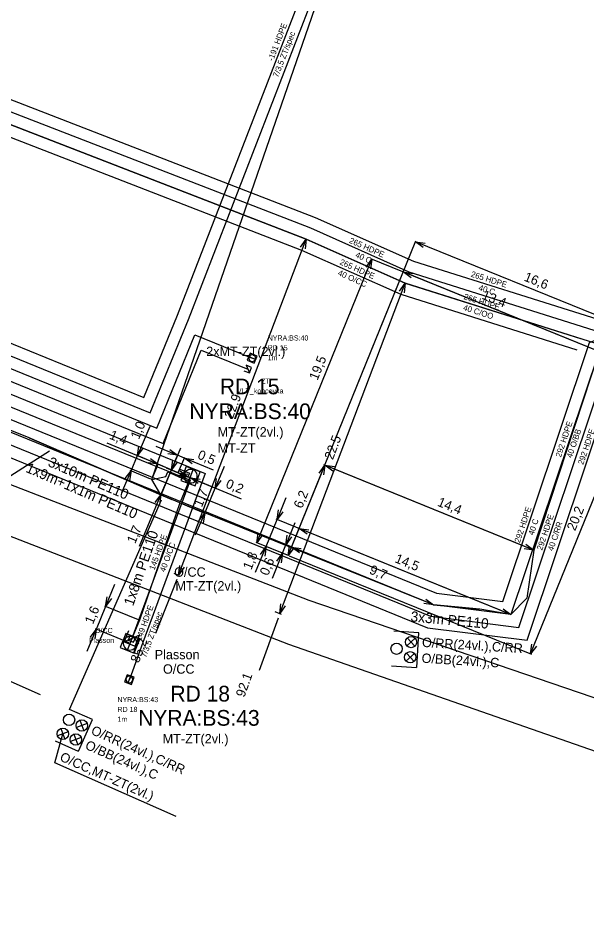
# Model space of a CAD drawing. Extents: x -836739 to -834468, y -1071001 to -1070126.
# Drawn here: x -836298 to -836261.8, y -1070459.3 to -1070401.3 of the extents above; entities that cross this region are included whole.
import ezdxf

# ---------------------------------------------------------------- set-up
doc = ezdxf.new("R2010")
doc.units = 0
for name, color, linetype in [('f001_pol_linie', 7, 'Continuous'), ('f002_inz_linie_mimo_CETIN', 7, 'Continuous'), ('f003_opt_sit_texty', 7, 'Continuous'), ('f003_opt_sit_znacky', 7, 'Continuous'), ('f006_osa_trasy', 7, 'Continuous'), ('f006_stp_koty', 7, 'Continuous'), ('f006_stp_linie', 7, 'Continuous'), ('f006_stp_texty', 7, 'Continuous'), ('f007_rezkynet_linie', 7, 'Continuous'), ('f007_rezkynet_texty', 7, 'Continuous'), ('f007_rezkynet_znacky', 7, 'Continuous'), ('f309_rozvadec_opt', 7, 'Continuous'), ('f309_rozvadec_opt_ann', 7, 'Continuous'), ('f309_trub_konc_zar', 7, 'Continuous'), ('f309_trub_konc_zar_ann', 7, 'Continuous'), ('f309_trubicka', 7, 'Continuous'), ('f309_trubicka_ann', 7, 'Continuous'), ('f309_trubka', 7, 'Continuous'), ('f309_trubka_ann', 7, 'Continuous')]:
    doc.layers.add(name, color=color, linetype=linetype)

msp = doc.modelspace()

# ---------------------------------------------------------------- linework, layer by layer
at = {"layer": 'f001_pol_linie'}
for points in [[(-836015.21, -1070459.49), (-836021.84, -1070470.53), (-836029.29, -1070480.55), (-836039.31, -1070497.89), (-836043.1, -1070509.87), (-836044.22, -1070522.08), (-836111.13, -1070487.77), (-836123.74, -1070483.53), (-836128.61, -1070481.99), (-836211.76, -1070460.38), (-836245.95, -1070449.75), (-836279.43, -1070438.33), (-836363.94, -1070405.58)], [(-836046.6, -1070544.35), (-836045.64, -1070538.23), (-836044.38, -1070528.39), (-836045.14, -1070525.37), (-836047.92, -1070523.71), (-836112.97, -1070490.6), (-836124.66, -1070486.54), (-836132.47, -1070484.33), (-836212.77, -1070463.28), (-836247.95, -1070452.55), (-836280.73, -1070441.12), (-836361.89, -1070409.63)]]:
    msp.add_lwpolyline(points, dxfattribs=at)
at = {"layer": 'f002_inz_linie_mimo_CETIN'}
for points in [[(-836287.77, -1070430.19), (-836287.67, -1070429.96), (-836287.05, -1070430.22), (-836287.15, -1070430.45)], [(-836287.77, -1070430.19), (-836287.67, -1070429.96), (-836287.05, -1070430.22), (-836287.15, -1070430.45)], [(-836287.77, -1070430.19), (-836287.15, -1070430.45)], [(-836287.77, -1070430.19), (-836287.15, -1070430.45)]]:
    msp.add_lwpolyline(points, dxfattribs=at)
at = {"layer": 'f003_opt_sit_znacky'}
for p, q in [((-836286.84, -1070430.005), (-836287.14, -1070430.815)), ((-836286.84, -1070430.006), (-836286.84, -1070430.005)), ((-836290.233, -1070440.531), (-836291.207, -1070440.949)), ((-836290.68, -1070440.639), (-836291, -1070441.441)), ((-836290.68, -1070440.64), (-836290.68, -1070440.639))]:
    msp.add_line(p, q, dxfattribs=at)
for points in [[(-836287.604, -1070430.694), (-836286.704, -1070431.028), (-836286.371, -1070430.127), (-836287.271, -1070429.794)], [(-836291.462, -1070441.308), (-836290.57, -1070441.665), (-836290.214, -1070440.774), (-836291.105, -1070440.417)]]:
    msp.add_lwpolyline(points, close=True, dxfattribs=at)
msp.add_lwpolyline([(-836290.929, -1070440.253), (-836291.207, -1070440.949), (-836290.511, -1070441.227), (-836290.233, -1070440.531)], dxfattribs=at)
for centre, start, end in [((-836286.987, -1070430.411), 70.04066, 249.31307), ((-836286.987, -1070430.411), 249.27232, 70.08055), ((-836290.837, -1070441.041), 68.56239, 247.83479), ((-836290.837, -1070441.042), 247.79404, 68.60228)]:
    msp.add_arc(centre, 0.432, start, end, dxfattribs=at)
at = {"layer": 'f006_osa_trasy'}
for points in [[(-836259.51, -1070422.49), (-836273.33, -1070418.13), (-836279.63, -1070415.33), (-836305.65, -1070405.26), (-836332.15, -1070395.46), (-836355.51, -1070386.15), (-836363.32, -1070381.37), (-836370.68, -1070374.62), (-836386.63, -1070361.4), (-836412.6, -1070344.19), (-836444.52, -1070318.16), (-836450.35, -1070293.64), (-836451.12, -1070284.95), (-836453.47, -1070277.02), (-836456.68, -1070270.62)], [(-836289.45, -1070430.62), (-836275.81, -1070391.2), (-836278.03, -1070390.26), (-836275.63, -1070384.47)], [(-836288.87, -1070431.6), (-836297.25, -1070427.97), (-836320.19, -1070418.75)], [(-836259.51, -1070422.49), (-836260.99, -1070422.47), (-836265.14, -1070435.11), (-836265.59, -1070438.17), (-836266.6, -1070439.21), (-836268.57, -1070438.87), (-836271.52, -1070438.59), (-836287.66, -1070432.1)], [(-836289.45, -1070430.62), (-836288.57, -1070430.43), (-836288.43, -1070430.13), (-836287.11, -1070430.72), (-836286.99, -1070430.41)], [(-836288.87, -1070431.6), (-836289.45, -1070430.62)], [(-836287.66, -1070432.1), (-836288.18, -1070431.9), (-836288.87, -1070431.6)], [(-836287.66, -1070432.1), (-836290.24, -1070439.58), (-836290.72, -1070440.74)], [(-836290.72, -1070440.74), (-836290.84, -1070441.04)]]:
    msp.add_lwpolyline(points, dxfattribs=at)
at = {"layer": 'f006_stp_koty'}
for p, q in [((-836280.747, -1070435.404), (-836272.651, -1070415.438)), ((-836257.247, -1070421.749), (-836272.673, -1070415.494)), ((-836282.764, -1070434.651), (-836275.447, -1070416.607)), ((-836261.046, -1070422.447), (-836275.503, -1070416.585)), ((-836280.747, -1070435.404), (-836273.43, -1070417.361)), ((-836260.99, -1070422.47), (-836273.453, -1070417.416)), ((-836265.343, -1070441.716), (-836257.77, -1070423.04)), ((-836289.584, -1070427.238), (-836290.366, -1070429.101)), ((-836292.317, -1070428.283), (-836289.045, -1070429.655)), ((-836289.196, -1070428.499), (-836287.813, -1070429.079)), ((-836287.623, -1070428.625), (-836288.203, -1070430.009)), ((-836290.771, -1070430.066), (-836290.366, -1070429.101)), ((-836287.825, -1070430.167), (-836290.421, -1070429.078)), ((-836288.847, -1070431.545), (-836287.79, -1070429.024)), ((-836287.38, -1070429.26), (-836287.813, -1070429.079)), ((-836287.747, -1070430.135), (-836287.357, -1070429.205)), ((-836285.527, -1070430.037), (-836287.38, -1070429.26)), ((-836291.351, -1070431.449), (-836290.771, -1070430.066)), ((-836289.505, -1070430.597), (-836290.826, -1070430.043)), ((-836289.427, -1070430.565), (-836289.022, -1070429.6)), ((-836287.77, -1070430.19), (-836289.045, -1070429.655)), ((-836288.87, -1070431.6), (-836288.203, -1070430.009)), ((-836288.533, -1070429.87), (-836287.15, -1070430.45)), ((-836287.825, -1070430.167), (-836288.258, -1070429.985)), ((-836284.843, -1070429.791), (-836285.423, -1070431.174)), ((-836280.77, -1070435.46), (-836278.441, -1070429.716)), ((-836280.747, -1070435.404), (-836278.418, -1070429.661)), ((-836265.196, -1070435.087), (-836278.496, -1070429.694)), ((-836265.14, -1070435.11), (-836278.441, -1070429.716)), ((-836286.387, -1070430.77), (-836287.77, -1070430.19)), ((-836287.637, -1070432.045), (-836286.972, -1070430.46)), ((-836287.15, -1070430.45), (-836286.995, -1070430.515)), ((-836287.095, -1070430.473), (-836285.367, -1070431.198)), ((-836283.738, -1070431.881), (-836286.995, -1070430.515)), ((-836286.088, -1070432.759), (-836285.423, -1070431.174)), ((-836290.237, -1070434.86), (-836288.87, -1070431.6)), ((-836280.922, -1070431.784), (-836281.485, -1070433.174)), ((-836287.605, -1070432.123), (-836286.032, -1070432.783)), ((-836286.668, -1070434.143), (-836286.088, -1070432.759)), ((-836282.181, -1070434.888), (-836281.485, -1070433.174)), ((-836266.656, -1070439.187), (-836281.541, -1070433.151)), ((-836280.355, -1070433.389), (-836280.919, -1070434.779)), ((-836280.747, -1070435.404), (-836280.052, -1070433.69)), ((-836266.6, -1070439.21), (-836280.075, -1070433.746)), ((-836280.826, -1070435.437), (-836282.82, -1070434.629)), ((-836281.135, -1070435.312), (-836280.919, -1070434.779)), ((-836271.576, -1070438.567), (-836280.974, -1070434.756)), ((-836282.846, -1070436.528), (-836282.181, -1070434.888)), ((-836280.826, -1070435.437), (-836282.236, -1070434.865)), ((-836281.777, -1070436.895), (-836281.135, -1070435.312)), ((-836280.826, -1070435.437), (-836281.191, -1070435.289)), ((-836280.747, -1070435.404), (-836280.531, -1070434.871)), ((-836271.52, -1070438.59), (-836280.554, -1070434.927)), ((-836280.714, -1070435.483), (-836265.288, -1070441.738)), ((-836291.821, -1070437.309), (-836292.391, -1070438.696)), ((-836292.391, -1070438.696), (-836292.991, -1070440.156)), ((-836290.295, -1070439.557), (-836292.447, -1070438.673)), ((-836293.561, -1070441.543), (-836292.991, -1070440.156)), ((-836290.895, -1070441.017), (-836293.047, -1070440.133))]:
    msp.add_line(p, q, dxfattribs=at)
for points in [[(-836287.75, -1070436.714), (-836279.63, -1070415.329)], [(-836279.983, -1070415.836), (-836279.63, -1070415.329), (-836279.702, -1070415.943)], [(-836272.174, -1070415.858), (-836272.673, -1070415.494), (-836272.061, -1070415.58)], [(-836275.812, -1070417.107), (-836275.447, -1070416.607), (-836275.534, -1070417.22)], [(-836272.953, -1070417.781), (-836273.453, -1070417.416), (-836272.841, -1070417.503)], [(-836281.315, -1070439.158), (-836273.329, -1070418.13)], [(-836273.682, -1070418.637), (-836273.329, -1070418.13), (-836273.401, -1070418.744)], [(-836289.996, -1070428.606), (-836290.366, -1070429.101), (-836290.272, -1070428.49)], [(-836288.308, -1070428.708), (-836287.813, -1070429.079), (-836288.424, -1070428.985)], [(-836289.541, -1070429.285), (-836289.045, -1070429.655), (-836289.657, -1070429.561)], [(-836287.832, -1070429.513), (-836288.203, -1070430.009), (-836288.109, -1070429.397)], [(-836286.885, -1070429.631), (-836287.38, -1070429.26), (-836286.769, -1070429.354)], [(-836291.141, -1070430.561), (-836290.771, -1070430.066), (-836290.864, -1070430.678)], [(-836287.645, -1070430.08), (-836287.15, -1070430.45), (-836287.761, -1070430.356)], [(-836278.805, -1070430.216), (-836278.441, -1070429.716), (-836278.527, -1070430.329)], [(-836277.941, -1070430.081), (-836278.441, -1070429.716), (-836277.828, -1070429.803)], [(-836287.275, -1070430.56), (-836287.77, -1070430.19), (-836287.159, -1070430.284)], [(-836286.5, -1070430.885), (-836286.995, -1070430.515), (-836286.384, -1070430.609)], [(-836285.052, -1070430.679), (-836285.423, -1070431.174), (-836285.329, -1070430.563)], [(-836289.24, -1070432.095), (-836288.87, -1070431.6), (-836288.964, -1070432.211)], [(-836286.458, -1070433.255), (-836286.088, -1070432.759), (-836286.181, -1070433.371)], [(-836281.121, -1070432.674), (-836281.485, -1070433.174), (-836281.399, -1070432.561)], [(-836282.4, -1070434.152), (-836282.764, -1070434.651), (-836282.678, -1070434.039)], [(-836280.554, -1070434.279), (-836280.919, -1070434.779), (-836280.832, -1070434.166)], [(-836279.575, -1070434.11), (-836280.075, -1070433.746), (-836279.462, -1070433.832)], [(-836265.64, -1070434.746), (-836265.14, -1070435.11), (-836265.752, -1070435.024)], [(-836282.545, -1070435.388), (-836282.181, -1070434.888), (-836282.267, -1070435.5)], [(-836281.5, -1070435.812), (-836281.135, -1070435.312), (-836281.222, -1070435.924)], [(-836280.406, -1070434.96), (-836280.77, -1070435.46), (-836280.684, -1070434.848)], [(-836280.054, -1070435.291), (-836280.554, -1070434.927), (-836279.941, -1070435.013)], [(-836287.396, -1070436.206), (-836287.75, -1070436.714), (-836287.677, -1070436.099)], [(-836287.861, -1070436.993), (-836289.213, -1070440.431)], [(-836287.787, -1070436.7), (-836288.031, -1070436.607)], [(-836292.024, -1070438.198), (-836292.391, -1070438.696), (-836292.302, -1070438.084)], [(-836272.02, -1070438.226), (-836271.52, -1070438.59), (-836272.132, -1070438.504)], [(-836280.961, -1070438.65), (-836281.315, -1070439.158), (-836281.242, -1070438.543)], [(-836267.1, -1070438.846), (-836266.6, -1070439.21), (-836267.212, -1070439.124)], [(-836281.193, -1070439.205), (-836281.596, -1070439.052)], [(-836281.418, -1070439.441), (-836282.619, -1070442.776)], [(-836293.358, -1070440.654), (-836292.991, -1070440.156), (-836293.081, -1070440.768)], [(-836264.979, -1070441.216), (-836265.343, -1070441.716), (-836265.257, -1070441.103)]]:
    msp.add_lwpolyline(points, dxfattribs=at)
at = {"layer": 'f006_stp_linie'}
for points in [[(-836297.25, -1070427.97), (-836288.87, -1070431.6)], [(-836288.87, -1070431.6), (-836288.18, -1070431.9)], [(-836287.66, -1070432.1), (-836290.24, -1070439.58)], [(-836271.52, -1070438.59), (-836268.57, -1070438.87)]]:
    msp.add_lwpolyline(points, dxfattribs=at)
at = {"layer": 'f007_rezkynet_linie'}
for points in [[(-836307.058, -1070435.86), (-836295.973, -1070428.796)], [(-836294.699, -1070445.249), (-836288.84, -1070431.91)], [(-836296.531, -1070444.332), (-836307.992, -1070439.257), (-836307.472, -1070437.416)], [(-836287.9, -1070452.07), (-836295.633, -1070448.646), (-836295.113, -1070446.805)]]:
    msp.add_lwpolyline(points, dxfattribs=at)
at = {"layer": 'f007_rezkynet_znacky'}
for p, q in [((-836272.456, -1070440.375), (-836274.053, -1070440.275)), ((-836272.594, -1070442.577), (-836272.456, -1070440.375)), ((-836272.682, -1070440.724), (-836273.226, -1070441.205)), ((-836273.194, -1070440.693), (-836272.713, -1070441.236)), ((-836272.732, -1070441.693), (-836273.276, -1070442.174)), ((-836273.244, -1070441.662), (-836272.763, -1070442.205)), ((-836274.207, -1070442.477), (-836272.61, -1070442.576)), ((-836293.236, -1070445.897), (-836294.699, -1070445.249)), ((-836293.568, -1070446.147), (-836294.246, -1070446.408)), ((-836294.129, -1070447.915), (-836293.236, -1070445.897)), ((-836294.038, -1070445.939), (-836293.776, -1070446.616)), ((-836294.774, -1070446.674), (-836295.452, -1070446.935)), ((-836295.244, -1070446.466), (-836294.982, -1070447.143)), ((-836294.422, -1070446.83), (-836294.159, -1070447.507)), ((-836295.607, -1070447.261), (-836294.144, -1070447.908)), ((-836293.952, -1070447.038), (-836294.629, -1070447.299))]:
    msp.add_line(p, q, dxfattribs=at)
for centre in [(-836273.872, -1070441.389), (-836272.954, -1070440.965), (-836273.004, -1070441.933), (-836294.721, -1070445.917), (-836293.907, -1070446.278), (-836295.113, -1070446.805), (-836294.291, -1070447.169)]:
    msp.add_circle(centre, 0.363, dxfattribs=at)
at = {"layer": 'f309_rozvadec_opt'}
for p, q in [((-836282.861, -1070422.981), (-836283.261, -1070422.818)), ((-836282.862, -1070422.981), (-836282.861, -1070422.981)), ((-836290.954, -1070443.552), (-836290.805, -1070443.147)), ((-836290.954, -1070443.552), (-836290.954, -1070443.552))]:
    msp.add_line(p, q, dxfattribs=at)
for points in [[(-836283.193, -1070422.588), (-836283.375, -1070423.032), (-836282.93, -1070423.214), (-836282.749, -1070422.769)], [(-836290.573, -1070443.207), (-836291.023, -1070443.041), (-836291.189, -1070443.491), (-836290.738, -1070443.657)]]:
    msp.add_lwpolyline(points, close=True, dxfattribs=at)
for centre, start, end in [((-836283.062, -1070422.901), 157.39472, 338.20296), ((-836283.062, -1070422.901), 338.16306, 157.43547), ((-836290.881, -1070443.349), 69.38754, 250.19578), ((-836290.881, -1070443.349), 250.15589, 69.42829)]:
    msp.add_arc(centre, 0.216, start, end, dxfattribs=at)
at = {"layer": 'f309_trub_konc_zar'}
for p, q in [((-836283.448, -1070423.351), (-836283.242, -1070423.839)), ((-836290.479, -1070440.629), (-836290.961, -1070440.851))]:
    msp.add_line(p, q, dxfattribs=at)
for points in [[(-836283.589, -1070423.698), (-836283.242, -1070423.839), (-836283.101, -1070423.492), (-836283.448, -1070423.351)], [(-836290.831, -1070440.499), (-836290.961, -1070440.851), (-836290.609, -1070440.981), (-836290.479, -1070440.629)]]:
    msp.add_lwpolyline(points, dxfattribs=at)
at = {"layer": 'f309_trubicka'}
for points in [[(-836400.273, -1070369.489), (-836399.069, -1070370.656), (-836400.13, -1070374.016), (-836402.617, -1070381.89), (-836396.907, -1070384.038), (-836379.536, -1070393.352), (-836349.287, -1070404.44), (-836286.052, -1070430.233), (-836290.016, -1070440.999), (-836290.881, -1070443.349)], [(-836400.273, -1070369.489), (-836396.208, -1070371.559), (-836397.27, -1070374.92), (-836399.339, -1070381.472), (-836399.355, -1070381.515), (-836396.285, -1070382.67), (-836378.92, -1070391.98), (-836348.745, -1070403.04), (-836289.137, -1070427.354), (-836286.713, -1070421.411), (-836283.062, -1070422.901)], [(-836400.273, -1070369.489), (-836394.777, -1070372.011), (-836395.84, -1070375.372), (-836397.495, -1070380.612), (-836395.663, -1070381.302), (-836378.304, -1070390.608), (-836348.203, -1070401.64), (-836289.959, -1070425.398), (-836287.821, -1070420.156), (-836276.772, -1070391.607), (-836279.008, -1070390.66), (-836276.322, -1070384.183), (-836278.31, -1070383.359), (-836277.858, -1070382.269)], [(-836400.273, -1070369.489), (-836395.493, -1070371.785), (-836396.555, -1070375.146), (-836398.424, -1070381.064), (-836395.974, -1070381.986), (-836378.612, -1070391.294), (-836348.474, -1070402.34), (-836289.548, -1070426.376), (-836287.124, -1070420.433), (-836275.81, -1070391.2), (-836278.03, -1070390.26), (-836275.63, -1070384.47), (-836273.812, -1070385.224), (-836273.367, -1070384.131)], [(-836397.141, -1070372.024), (-836397.985, -1070374.694), (-836400.049, -1070381.229), (-836400.305, -1070381.924), (-836400.312, -1070381.956), (-836396.596, -1070383.354), (-836379.228, -1070392.666), (-836349.016, -1070403.74), (-836288.726, -1070428.332), (-836286.302, -1070422.389), (-836283.345, -1070423.595)]]:
    msp.add_lwpolyline(points, dxfattribs=at)
at = {"layer": 'f309_trubka'}
for points in [[(-836261.299, -1070421.137), (-836273.064, -1070417.427), (-836279.342, -1070414.637), (-836305.385, -1070404.559), (-836331.881, -1070394.76), (-836354.106, -1070385.902), (-836354.759, -1070385.663), (-836362.708, -1070381.226), (-836386.046, -1070360.976), (-836412.515, -1070343.515), (-836444.58, -1070317.908), (-836450.178, -1070294.362), (-836450.35, -1070293.64), (-836451.12, -1070284.95), (-836453.47, -1070277.02), (-836455.659, -1070272.655)], [(-836454.989, -1070272.319), (-836452.77, -1070276.743), (-836450.38, -1070284.809), (-836449.608, -1070293.52), (-836449.436, -1070294.242), (-836443.91, -1070317.483), (-836412.074, -1070342.908), (-836385.592, -1070360.377), (-836362.275, -1070380.609), (-836354.445, -1070384.979), (-836353.838, -1070385.201), (-836331.612, -1070394.06), (-836305.12, -1070403.858), (-836279.054, -1070413.944), (-836272.798, -1070416.724), (-836261.073, -1070420.421)], [(-836457, -1070273.327), (-836454.87, -1070277.574), (-836452.6, -1070285.232), (-836451.834, -1070293.88), (-836451.663, -1070294.602), (-836445.92, -1070318.758), (-836413.397, -1070344.729), (-836386.954, -1070362.174), (-836363.574, -1070382.46), (-836355.387, -1070387.031), (-836354.642, -1070387.304), (-836332.419, -1070396.16), (-836305.915, -1070405.961), (-836279.918, -1070416.023), (-836273.596, -1070418.833), (-836262.401, -1070422.363)], [(-836456.329, -1070272.991), (-836454.17, -1070277.297), (-836451.86, -1070285.091), (-836451.092, -1070293.76), (-836445.25, -1070318.333), (-836412.956, -1070344.122), (-836386.5, -1070361.575), (-836363.141, -1070381.843), (-836355.073, -1070386.347), (-836354.374, -1070386.603), (-836332.15, -1070395.46), (-836305.65, -1070405.26), (-836279.63, -1070415.33), (-836273.33, -1070418.13), (-836262.175, -1070421.648)], [(-836257.543, -1070422.322), (-836258.258, -1070422.096), (-836259.283, -1070421.772), (-836260.99, -1070422.47), (-836266.6, -1070439.21), (-836271.52, -1070438.59), (-836350.1, -1070406.54), (-836380.46, -1070395.41), (-836397.84, -1070386.09), (-836408, -1070382.27), (-836428.93, -1070370.15), (-836446.35, -1070358.45), (-836497.8, -1070313.84), (-836500.259, -1070310.812)], [(-836499.139, -1070311.001), (-836497.259, -1070313.316), (-836445.894, -1070357.853), (-836428.533, -1070369.513), (-836407.678, -1070381.59), (-836397.529, -1070385.406), (-836380.152, -1070394.724), (-836349.829, -1070405.84), (-836271.328, -1070437.858), (-836267.116, -1070438.389), (-836261.592, -1070421.906), (-836259.316, -1070420.975), (-836258.032, -1070421.38), (-836257.317, -1070421.606)], [(-836501.069, -1070312.194), (-836498.882, -1070314.888), (-836447.262, -1070359.644), (-836429.724, -1070371.424), (-836408.644, -1070383.63), (-836398.462, -1070387.458), (-836381.076, -1070396.782), (-836350.642, -1070407.94), (-836271.904, -1070440.054), (-836265.568, -1070440.852), (-836259.786, -1070423.598), (-836259.218, -1070423.366), (-836257.995, -1070423.753)], [(-836499.902, -1070312.441), (-836498.341, -1070314.364), (-836446.806, -1070359.047), (-836429.327, -1070370.787), (-836408.322, -1070382.95), (-836398.151, -1070386.774), (-836380.768, -1070396.096), (-836350.371, -1070407.24), (-836271.712, -1070439.322), (-836266.084, -1070440.031), (-836260.388, -1070423.034), (-836259.25, -1070422.569), (-836257.769, -1070423.038)], [(-836400.845, -1070373.79), (-836403.452, -1070382.042), (-836403.525, -1070382.35), (-836397.218, -1070384.722), (-836379.844, -1070394.038), (-836349.558, -1070405.14), (-836287.006, -1070430.654), (-836290.72, -1070440.74)]]:
    msp.add_lwpolyline(points, dxfattribs=at)

# ---------------------------------------------------------------- texts
at = {"layer": 'f003_opt_sit_texty'}
for s, height, p in [('2xMT-ZT(2vl.)', 0.6, (-836285.99, -1070422.77)), ('RD 15', 1, (-836285.12, -1070425.2)), ('NYRA:BS:40', 1, (-836287.06, -1070426.78)), ('MT-ZT(2vl.)', 0.6, (-836285.26, -1070427.89)), ('MT-ZT', 0.6, (-836285.26, -1070428.92)), ('O/CC', 0.6, (-836288.03, -1070436.81)), ('MT-ZT(2vl.)', 0.6, (-836287.95, -1070437.69)), ('Plasson', 0.6, (-836289.27, -1070442.06)), ('O/CC', 0.6, (-836288.74, -1070442.98)), ('RD 18', 1, (-836288.27, -1070444.75)), ('NYRA:BS:43', 1, (-836290.32, -1070446.29)), ('MT-ZT(2vl.)', 0.6, (-836288.76, -1070447.42))]:
    msp.add_text(s, height=height, dxfattribs=at).set_placement(p)
at = {"layer": 'f006_stp_koty'}
for s, rotation, p in [('16,6', 337.92686, (-836265.812, -1070417.952)), ('13,4', 337.92686, (-836268.488, -1070419.106)), ('19,5', 67.92686, (-836278.911, -1070424.351)), ('22.9', 69.21, (-836284.302, -1070426.786)), ('1,0', 67.24902, (-836290.276, -1070428.11)), ('1,4', 337.24902, (-836292.201, -1070428.006)), ('22.5', 69.2, (-836277.934, -1070429.409)), ('0,5', 337.24902, (-836286.587, -1070429.267)), ('0,2', 337.24902, (-836284.798, -1070431.111)), ('1,7', 67.24902, (-836286.271, -1070432.422)), ('6,2', 67.92686, (-836279.897, -1070432.509)), ('14,4', 337.92686, (-836271.321, -1070432.28)), ('20,2', 67.92686, (-836262.51, -1070433.93)), ('1,7', 67.24902, (-836290.514, -1070434.744)), ('1,8', 67.92686, (-836283.124, -1070436.415)), ('0,6', 67.92686, (-836282.055, -1070436.783)), ('14,5', 337.92686, (-836274.03, -1070435.873)), ('9,7', 337.92686, (-836275.654, -1070436.59)), ('1,6', 67.65935, (-836293.197, -1070439.868)), ('85.2', 68.53, (-836290.285, -1070442.336)), ('92.1', 70.19, (-836283.566, -1070444.521))]:
    msp.add_text(s, height=0.6, rotation=rotation, dxfattribs=at).set_placement(p)
at = {"layer": 'f006_stp_texty'}
for s, rotation, p in [('3x10m PE110', 336.57898, (-836296.115, -1070429.748)), ('1x9m+1x1m PE110', 336.57898, (-836297.523, -1070430.123)), ('1x8m PE110', 70.96967, (-836290.645, -1070438.712)), ('3x3m PE110', 354.578, (-836273.003, -1070439.648))]:
    msp.add_text(s, height=0.65, rotation=rotation, dxfattribs=at).set_placement(p)
at = {"layer": 'f007_rezkynet_texty'}
for s, rotation, p in [('O/RR(24vl.),C/RR', 356.43561, (-836272.27, -1070441.27)), ('O/BB(24vl.),C', 356.43561, (-836272.295, -1070442.277)), ('O/RR(24vl.),C/RR', 336.11529, (-836293.372, -1070446.801)), ('O/BB(24vl.),C', 336.11529, (-836293.745, -1070447.737)), ('O/CC,MT-ZT(2vl.)', 336.11529, (-836295.36, -1070448.487))]:
    msp.add_text(s, height=0.6, rotation=rotation, dxfattribs=at).set_placement(p)
at = {"layer": 'f309_rozvadec_opt_ann'}
for s, p in [('NYRA:BS:40', (-836282.08, -1070421.778)), ('RD 15', (-836282.08, -1070422.403)), ('1m', (-836282.08, -1070423.028)), ('NYRA:BS:43', (-836291.64, -1070444.788)), ('RD 18', (-836291.64, -1070445.413)), ('1m', (-836291.64, -1070446.038))]:
    msp.add_text(s, height=0.325, dxfattribs=at).set_placement(p)
at = {"layer": 'f309_trub_konc_zar_ann'}
for s, p in [('ZT', (-836282.487, -1070424.52)), ('VLT_koncovka', (-836284.039, -1070425.145)), ('O/CC', (-836293.066, -1070440.39)), ('Plasson', (-836293.451, -1070441.015))]:
    msp.add_text(s, height=0.325, dxfattribs=at).set_placement(p)
at = {"layer": 'f309_trubicka_ann'}
for s, rotation, p in [('-191 HDPE', 68.84263, (-836281.741, -1070404.03)), ('7/3,5 ZT/spec', 68.84263, (-836281.417, -1070405.063)), ('-149 HDPE', 69.78649, (-836290.205, -1070441.077)), ('7/3,5 ZT/spec', 69.78649, (-836289.82, -1070441.985))]:
    msp.add_text(s, height=0.375, rotation=rotation, dxfattribs=at).set_placement(p)
at = {"layer": 'f309_trubka_ann'}
for s, rotation, p in [('265 HDPE', 336.0392, (-836276.924, -1070415.547)), ('40 O', 336.0392, (-836276.535, -1070416.459)), ('265 HDPE', 336.03583, (-836277.534, -1070416.918)), ('40 O/CC', 336.03583, (-836277.65, -1070417.605)), ('265 HDPE', 342.49946, (-836269.177, -1070417.708)), ('40 C', 342.49946, (-836268.688, -1070418.571)), ('265 HDPE', 342.49607, (-836269.628, -1070419.14)), ('40 C/OO', 342.49607, (-836269.667, -1070419.836)), ('292 HDPE', 71.47269, (-836263.415, -1070429.235)), ('40 O/BB', 71.47269, (-836262.719, -1070429.282)), ('292 HDPE', 71.47345, (-836261.993, -1070429.712)), ('292 HDPE', 71.47229, (-836266.031, -1070434.678)), ('292 HDPE', 71.47307, (-836264.608, -1070435.154)), ('40 C', 71.47229, (-836265.158, -1070434.2)), ('40 C/RR', 71.47307, (-836263.912, -1070435.201)), ('145 HDPE', 69.78462, (-836289.287, -1070436.415)), ('40 O/CC', 69.78462, (-836288.614, -1070436.541))]:
    msp.add_text(s, height=0.375, rotation=rotation, dxfattribs=at).set_placement(p)

doc.saveas('drawing.dxf')
